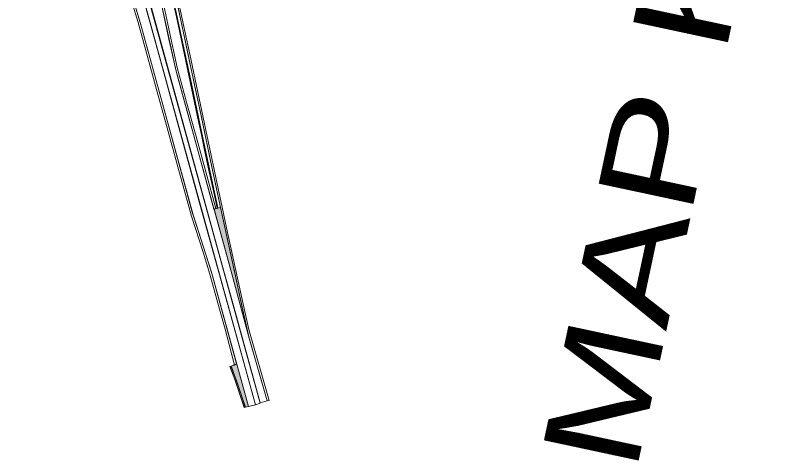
# Model space of a CAD drawing. Extents: x 2363411 to 2369702, y 6977197 to 6988655.
# Drawn here: x 2365788.3 to 2365962.6, y 6977645.3 to 6977745.7 of the extents above; entities that cross this region are included whole.
import ezdxf

# ---------------------------------------------------------------- set-up
doc = ezdxf.new("R2010")
doc.units = 0
doc.header["$LTSCALE"] = 5.6
for name, color, linetype, lineweight in [('10', 7, 'Continuous', 13), ('11', 7, 'Continuous', 13), ('62', 7, 'Continuous', 25)]:
    doc.layers.add(name, color=color, linetype=linetype, lineweight=lineweight)

msp = doc.modelspace()

# ---------------------------------------------------------------- hatches: boundary and pattern name
at = {"layer": '10'}
msp.add_hatch(color=256, dxfattribs=at).paths.add_polyline_path([(2365839.896, 6977657.239), (2365838.708, 6977660.883), (2365837.825, 6977663.546), (2365836.674, 6977666.505), (2365836.93, 6977666.598), (2365837.907, 6977664.082), (2365838.707, 6977661.711), (2365840.174, 6977657.311)])
at = {"layer": '11'}
for points in [[(2365834.568, 6977702.418), (2365833.093, 6977702.012), (2365837.11, 6977687.427), (2365840.904, 6977673.401)], [(2365837.572, 6977666.844), (2365837.519, 6977666.894), (2365837.669, 6977666.803), (2365838.229, 6977667.057), (2365840.849, 6977657.514), (2365840.156, 6977657.313), (2365838.936, 6977661.07), (2365838.319, 6977662.924), (2365837.714, 6977664.467), (2365837.232, 6977665.857), (2365836.987, 6977666.586)]]:
    msp.add_hatch(color=256, dxfattribs=at).paths.add_polyline_path(points)

# ---------------------------------------------------------------- linework, layer by layer
at = {"layer": '10'}
for points in [[(2365789.252, 6977846.871), (2365788.983, 6977848.809), (2365788.705, 6977850.827), (2365788.252, 6977854.43), (2365792.234, 6977840.111), (2365795.564, 6977827.998), (2365842.426, 6977657.89), (2365840.849, 6977657.514), (2365838.229, 6977667.057), (2365832.502, 6977687.816), (2365828.393, 6977700.702), (2365816.563, 6977743.6), (2365813.01, 6977755.509), (2365809.629, 6977765.357), (2365810.646, 6977765.816), (2365811.508, 6977766.069)], [(2365842.426, 6977657.889), (2365836.241, 6977680.434), (2365829.919, 6977703.146), (2365821.015, 6977735.548), (2365812.162, 6977767.642), (2365805.542, 6977791.676), (2365800.177, 6977811.198), (2365795.547, 6977827.746), (2365796.762, 6977827.449), (2365800.339, 6977815.413), (2365802.034, 6977810.073), (2365807.476, 6977789.437), (2365814.852, 6977762.071), (2365822.143, 6977735.563), (2365843.534, 6977658.26)], [(2365833.085, 6977702.01), (2365828.834, 6977717.477), (2365824.372, 6977733.735), (2365823.392, 6977738.376), (2365820.282, 6977752.732), (2365817.321, 6977766.519), (2365816.212, 6977771.662), (2365814.162, 6977781.093), (2365812.855, 6977786.464), (2365811.074, 6977793.073), (2365808.574, 6977802.497), (2365808.981, 6977802.614), (2365810.368, 6977797.428), (2365811.469, 6977793.335), (2365813.612, 6977785.209), (2365814.515, 6977781.398), (2365816.217, 6977773.741), (2365818.115, 6977764.933), (2365821.067, 6977751.173), (2365822.903, 6977742.733), (2365824.777, 6977734.009), (2365826.895, 6977726.172), (2365829.405, 6977717.073), (2365833.507, 6977702.177)], [(2365818.124, 6977750.562), (2365829.52, 6977709.104), (2365835.345, 6977688.04), (2365837.366, 6977680.786), (2365843.545, 6977658.293), (2365845.101, 6977658.739), (2365840.904, 6977673.401), (2365837.11, 6977687.427), (2365824.762, 6977732.219), (2365824.362, 6977733.813), (2365822.923, 6977740.355), (2365820.625, 6977751.118)], [(2365839.896, 6977657.239), (2365838.708, 6977660.883), (2365837.825, 6977663.546), (2365836.674, 6977666.505), (2365836.93, 6977666.598), (2365837.907, 6977664.082), (2365838.707, 6977661.711), (2365840.174, 6977657.311)]]:
    msp.add_lwpolyline(points, close=True, dxfattribs=at)
for points in [[(2365812.924, 6977755.695), (2365816.469, 6977743.93), (2365821.662, 6977725.055), (2365825.848, 6977709.897), (2365828.196, 6977701.354), (2365829.505, 6977697.163), (2365831.23, 6977691.79), (2365832.605, 6977687.526), (2365838.188, 6977667.084), (2365837.727, 6977666.843), (2365835.59, 6977674.97), (2365834.343, 6977679.417), (2365832.18, 6977687.369), (2365830.612, 6977692.303), (2365828.024, 6977700.423), (2365826.676, 6977705.328), (2365824.94, 6977711.582), (2365822.729, 6977719.542), (2365819.895, 6977729.833), (2365815.947, 6977744.157), (2365813.507, 6977752.288)], [(2365823.815, 6977749.953), (2365825.411, 6977742.462), (2365827.007, 6977734.905), (2365830.132, 6977720.195), (2365833.944, 6977702.271), (2365833.788, 6977702.226), (2365832.956, 6977706.158), (2365832.034, 6977710.436), (2365830.983, 6977715.34), (2365830.26, 6977718.823), (2365829.612, 6977721.805), (2365828.087, 6977728.978), (2365824.978, 6977743.662), (2365823.501, 6977750.63)], [(2365825.161, 6977748.458), (2365827.597, 6977736.983), (2365830.63, 6977722.7), (2365833.489, 6977709.124), (2365834.939, 6977702.474), (2365835.928, 6977697.786), (2365839.452, 6977681.646), (2365840.959, 6977674.845), (2365845.532, 6977658.87), (2365845.109, 6977658.76), (2365840.957, 6977673.218), (2365840.07, 6977677.238), (2365839.637, 6977679.156), (2365837.937, 6977686.987), (2365834.57, 6977702.436), (2365832.379, 6977712.642), (2365829.483, 6977726.296), (2365827.711, 6977734.682), (2365824.69, 6977748.923)]]:
    msp.add_lwpolyline(points, dxfattribs=at)
at = {"layer": '11'}
msp.add_lwpolyline([(2365824.506, 6977746.738), (2365827.768, 6977731.395), (2365830.302, 6977719.57), (2365833.932, 6977702.311), (2365833.96, 6977702.251), (2365834.568, 6977702.418), (2365832.11, 6977714.01), (2365830.31, 6977722.498), (2365828.763, 6977729.676), (2365827.015, 6977737.977), (2365825.743, 6977743.913), (2365823.841, 6977752.779)], dxfattribs=at)
for points in [[(2365834.568, 6977702.418), (2365833.093, 6977702.012), (2365837.11, 6977687.427), (2365840.904, 6977673.401)], [(2365837.572, 6977666.844), (2365837.519, 6977666.894), (2365837.669, 6977666.803), (2365838.229, 6977667.057), (2365840.849, 6977657.514), (2365840.156, 6977657.313), (2365838.936, 6977661.07), (2365838.319, 6977662.924), (2365837.714, 6977664.467), (2365837.232, 6977665.857), (2365836.987, 6977666.586)]]:
    msp.add_lwpolyline(points, close=True, dxfattribs=at)

# ---------------------------------------------------------------- texts
at = {"layer": '62', "width": 1.35}
msp.add_text('MAP KEY', height=21.87, rotation=77.939, dxfattribs=at).set_placement((2365928.313, 6977642.122))

doc.saveas('drawing.dxf')
